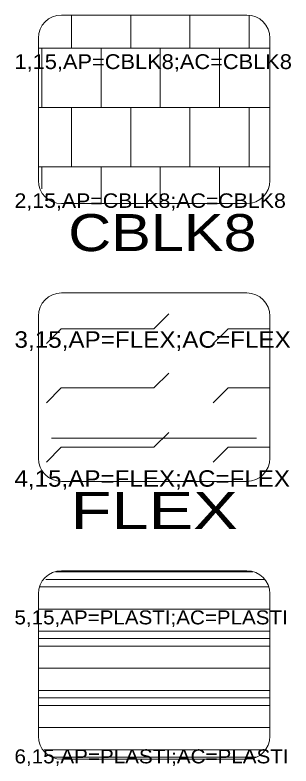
# Model space of a CAD drawing. Extents: x 95935 to 95946.4, y 95971.2 to 95974.7.
# Drawn here: x 95943.435 to 95944.031, y 95973.11 to 95974.732 of the extents above; entities that cross this region are included whole.
import ezdxf
from ezdxf.enums import TextEntityAlignment as Align

# ---------------------------------------------------------------- set-up
doc = ezdxf.new("R2010")
doc.units = 0
doc.header["$LTSCALE"] = 0.013
for name, color, linetype, lineweight in [('1', 7, 'Continuous', 13), ('25', 7, 'Continuous', 13), ('6', 7, 'Continuous', 13), ('63', 7, 'Continuous', 13)]:
    doc.layers.add(name, color=color, linetype=linetype, lineweight=lineweight)
doc.layers.add('20', color=7, linetype='Continuous')

msp = doc.modelspace()

# ---------------------------------------------------------------- linework, layer by layer
at = {"layer": '1'}
for p, q in [((95943.5357, 95974.7318), (95943.9357, 95974.7318)), ((95943.4857, 95974.3747), (95943.4857, 95974.6818)), ((95943.9857, 95974.6818), (95943.9857, 95974.3747)), ((95943.9357, 95974.3247), (95943.5357, 95974.3247)), ((95943.5357, 95974.1318), (95943.9357, 95974.1318)), ((95943.4857, 95973.7747), (95943.4857, 95974.0818)), ((95943.9857, 95974.0818), (95943.9857, 95973.7747)), ((95943.9357, 95973.7247), (95943.5357, 95973.7247)), ((95943.5357, 95973.5318), (95943.9357, 95973.5318)), ((95943.4857, 95973.1747), (95943.4857, 95973.4818)), ((95943.9857, 95973.4818), (95943.9857, 95973.1747)), ((95943.9357, 95973.1247), (95943.5357, 95973.1247))]:
    msp.add_line(p, q, dxfattribs=at)
for centre, start, end in [((95943.5357, 95974.6818), 90, 180), ((95943.9357, 95974.6818), 0, 90), ((95943.5357, 95974.3747), 180, 270), ((95943.9357, 95974.3747), 270, 0), ((95943.5357, 95974.0818), 90, 180), ((95943.9357, 95974.0818), 0, 90), ((95943.5357, 95973.7747), 180, 270), ((95943.9357, 95973.7747), 270, 0), ((95943.5357, 95973.4818), 90, 180), ((95943.9357, 95973.4818), 0, 90), ((95943.5357, 95973.1747), 180, 270), ((95943.9357, 95973.1747), 270, 0)]:
    msp.add_arc(centre, 0.05, start, end, dxfattribs=at)
at = {"layer": '25'}
msp.add_line((95943.9569, 95973.8178), (95943.5141, 95973.8178), dxfattribs=at)
at = {"layer": '6'}
for p, q in [((95943.5571, 95974.6601), (95943.5571, 95974.7318)), ((95943.6851, 95974.6601), (95943.6851, 95974.7318)), ((95943.8131, 95974.6601), (95943.8131, 95974.7318)), ((95943.9411, 95974.6601), (95943.9411, 95974.7307)), ((95943.4857, 95974.6601), (95943.9857, 95974.6601)), ((95943.4931, 95974.5321), (95943.4931, 95974.6601)), ((95943.6211, 95974.5321), (95943.6211, 95974.6601)), ((95943.7491, 95974.5321), (95943.7491, 95974.6601)), ((95943.8771, 95974.5321), (95943.8771, 95974.6601)), ((95943.4857, 95974.5321), (95943.9857, 95974.5321)), ((95943.5571, 95974.4041), (95943.5571, 95974.5321)), ((95943.6851, 95974.4041), (95943.6851, 95974.5321)), ((95943.8131, 95974.4041), (95943.8131, 95974.5321)), ((95943.9411, 95974.4041), (95943.9411, 95974.5321)), ((95943.4857, 95974.4041), (95943.9857, 95974.4041)), ((95943.4931, 95974.3568), (95943.4931, 95974.4041)), ((95943.6211, 95974.3247), (95943.6211, 95974.4041)), ((95943.7491, 95974.3247), (95943.7491, 95974.4041)), ((95943.8771, 95974.3247), (95943.8771, 95974.4041)), ((95943.5033, 95974.0225), (95943.5353, 95974.0545)), ((95943.8633, 95974.0225), (95943.8953, 95974.0545)), ((95943.8953, 95974.0545), (95943.9857, 95974.0545)), ((95943.5033, 95973.8945), (95943.5353, 95973.9265)), ((95943.8633, 95973.8945), (95943.8953, 95973.9265)), ((95943.8953, 95973.9265), (95943.9857, 95973.9265)), ((95943.5033, 95973.7665), (95943.5353, 95973.7985)), ((95943.8633, 95973.7665), (95943.8953, 95973.7985)), ((95943.8953, 95973.7985), (95943.9857, 95973.7985)), ((95943.5226, 95973.5292), (95943.9488, 95973.5292)), ((95943.5018, 95973.5132), (95943.9738, 95973.5132)), ((95943.4888, 95973.4972), (95943.9826, 95973.4972)), ((95943.4857, 95973.4492), (95943.9857, 95973.4492)), ((95943.4857, 95973.4012), (95943.9857, 95973.4012)), ((95943.4857, 95973.3852), (95943.9857, 95973.3852)), ((95943.4857, 95973.3692), (95943.9857, 95973.3692)), ((95943.4857, 95973.3212), (95943.9857, 95973.3212)), ((95943.4857, 95973.2732), (95943.9857, 95973.2732)), ((95943.4857, 95973.2572), (95943.9857, 95973.2572)), ((95943.4857, 95973.2412), (95943.9857, 95973.2412)), ((95943.4857, 95973.1932), (95943.9857, 95973.1932)), ((95943.4979, 95973.1452), (95943.975, 95973.1452)), ((95943.5155, 95973.1292), (95943.9559, 95973.1292))]:
    msp.add_line(p, q, dxfattribs=at)
for points in [[(95943.5353, 95974.0545), (95943.7353, 95974.0545), (95943.7673, 95974.0865)], [(95943.5353, 95973.9265), (95943.7353, 95973.9265), (95943.7673, 95973.9585)], [(95943.5353, 95973.7985), (95943.7353, 95973.7985), (95943.7673, 95973.8305)]]:
    msp.add_lwpolyline(points, dxfattribs=at)

# ---------------------------------------------------------------- texts
at = {"layer": '20'}
for s, width, p in [(' CBLK8', 1.2, (95943.7358, 95974.222)), (' FLEX ', 1.35, (95943.7358, 95973.622))]:
    msp.add_text(s, height=0.08, dxfattribs=dict(at, width=width)).set_placement(p, align=Align.CENTER)
at = {"layer": '63', "width": 1.1}
for s, height, p in [('1,15,AP=CBLK8;AC=CBLK8', 0.032, (95943.4341, 95974.6151)), ('2,15,AP=CBLK8;AC=CBLK8', 0.0313, (95943.4341, 95974.3154)), ('3,15,AP=FLEX;AC=FLEX', 0.0356, (95943.4341, 95974.0133)), ('4,15,AP=FLEX;AC=FLEX', 0.0355, (95943.4341, 95973.7133)), ('5,15,AP=PLASTI;AC=PLASTI', 0.0302, (95943.4341, 95973.416)), ('6,15,AP=PLASTI;AC=PLASTI', 0.0303, (95943.4341, 95973.1159))]:
    msp.add_text(s, height=height, dxfattribs=at).set_placement(p)

doc.saveas('drawing.dxf')
